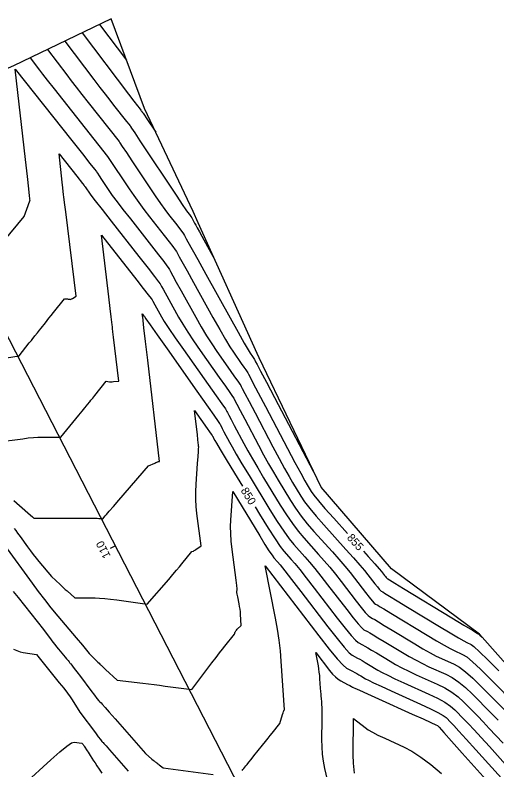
# Model space of a CAD drawing. Extents: x 1715724 to 1716561, y 394063 to 395906.
# Drawn here: x 1715894.2 to 1715978.1, y 395302.7 to 395434.3 of the extents above; entities that cross this region are included whole.
import ezdxf

# ---------------------------------------------------------------- set-up
doc = ezdxf.new("R2010")
doc.units = 0
for name, color, linetype in [('DT_X_Contour_Major', 7, 'Continuous'), ('DT_X_Contour_Minor', 7, 'Continuous'), ('DT_X_TIN_Hull', 7, 'Continuous'), ('GE_P_CL_10', 7, 'Continuous')]:
    doc.layers.add(name, color=color, linetype=linetype)

msp = doc.modelspace()

# ---------------------------------------------------------------- linework, layer by layer
at = {"layer": 'DT_X_Contour_Major'}
for points in [[(1715896.77, 395426.83), (1715898.41, 395424.66), (1715898.92, 395423.99), (1715899.77, 395422.9), (1715900.95, 395421.41), (1715902.46, 395419.51), (1715910.28, 395409.64), (1715914.02, 395404), (1715914.85, 395402.79), (1715915.71, 395401.57), (1715916.61, 395400.35), (1715917.56, 395399.12), (1715920.13, 395395.85), (1715920.99, 395394.75), (1715921.63, 395393.92), (1715922.05, 395393.35), (1715922.26, 395393.05), (1715922.51, 395392.59), (1715922.75, 395392.15), (1715924.12, 395389.68), (1715925.24, 395387.66), (1715928.63, 395381.54), (1715929.81, 395379.44), (1715930.8, 395377.73), (1715931.6, 395376.42), (1715932.21, 395375.49), (1715933.58, 395373.54), (1715934.04, 395372.89), (1715934.38, 395372.4), (1715934.6, 395372.08), (1715934.7, 395371.91), (1715934.82, 395371.68), (1715935.04, 395371.26), (1715935.61, 395370.18), (1715936.53, 395368.44), (1715937.79, 395366.03), (1715941.64, 395358.72), (1715942.93, 395356.27), (1715943.93, 395354.4), (1715944.64, 395353.1), (1715945.05, 395352.37), (1715945.76, 395351.21), (1715946.2, 395350.59), (1715947, 395349.61), (1715948.16, 395348.27), (1715949.68, 395346.57), (1715952.07, 395343.93)], [(1715894, 395344.79), (1715894.28, 395344.41), (1715894.59, 395343.98), (1715895.03, 395343.37), (1715896.34, 395341.55), (1715896.84, 395340.88), (1715897.32, 395340.24), (1715897.81, 395339.63), (1715898.29, 395339.05), (1715900.52, 395336.4), (1715902, 395335.01), (1715902.31, 395334.71), (1715902.61, 395334.43), (1715902.91, 395334.15), (1715903.21, 395333.89), (1715904.56, 395332.67), (1715908.09, 395332.66), (1715908.89, 395332.64), (1715909.79, 395332.58), (1715910.79, 395332.47), (1715911.88, 395332.33), (1715917.2, 395331.57), (1715920.92, 395335.88), (1715921.67, 395336.74), (1715922.3, 395337.49), (1715922.82, 395338.12), (1715923.24, 395338.63), (1715924.93, 395340.74), (1715925.16, 395340.82), (1715925.23, 395340.85), (1715925.34, 395340.91), (1715925.48, 395341), (1715925.67, 395341.12), (1715926.6, 395341.74), (1715925.84, 395347.36), (1715925.71, 395348.59), (1715925.65, 395349.85), (1715925.65, 395351.15), (1715925.71, 395352.49), (1715925.96, 395356.12), (1715926.04, 395357.32), (1715926.1, 395358.19), (1715926.14, 395358.74), (1715926.15, 395358.97), (1715926.14, 395359.15), (1715926.13, 395359.33), (1715926.08, 395359.71), (1715926.02, 395360.3), (1715925.92, 395361.1), (1715925.43, 395365.34), (1715927.62, 395362.22), (1715928.03, 395361.64), (1715928.33, 395361.22), (1715928.51, 395360.97), (1715928.57, 395360.88), (1715928.58, 395360.87), (1715928.59, 395360.84), (1715928.62, 395360.78), (1715928.67, 395360.68), (1715928.74, 395360.54), (1715928.96, 395360.13), (1715929.24, 395359.66), (1715929.91, 395358.55), (1715930.96, 395356.81), (1715932.4, 395354.44), (1715933.79, 395352.15)], [(1715935.97, 395348.56), (1715936.76, 395347.26), (1715938.26, 395344.84), (1715939.46, 395342.96), (1715940.37, 395341.61), (1715941, 395340.81), (1715942.28, 395339.39), (1715942.89, 395338.68), (1715943.76, 395337.61), (1715944.89, 395336.18), (1715946.27, 395334.39), (1715950.31, 395329.15), (1715951.68, 395327.41), (1715952.73, 395326.12), (1715953.48, 395325.29), (1715953.93, 395324.9), (1715954.72, 395324.49), (1715955.09, 395324.29), (1715955.61, 395323.99), (1715956.28, 395323.59), (1715957.11, 395323.09), (1715959.51, 395321.63), (1715960.47, 395321.07), (1715961.55, 395320.49), (1715962.75, 395319.9), (1715964.07, 395319.29), (1715967.73, 395317.64), (1715969.05, 395316.98), (1715970.26, 395316.24), (1715971.34, 395315.43), (1715972.32, 395314.54), (1715974.77, 395312.05), (1715975.74, 395311.06), (1715976.79, 395309.94), (1715977.94, 395308.7), (1715979.19, 395307.33)], [(1715954.88, 395340.81), (1715955.71, 395339.89), (1715956.85, 395338.62), (1715957.61, 395337.75), (1715957.99, 395337.29), (1715958.51, 395336.61), (1715958.69, 395336.39), (1715958.83, 395336.22), (1715958.93, 395336.11), (1715958.98, 395336.06), (1715959.09, 395336.01), (1715959.42, 395335.81), (1715960.33, 395335.25), (1715961.84, 395334.34), (1715970.28, 395329.2), (1715972.37, 395327.94), (1715973.86, 395327.03), (1715974.76, 395326.48), (1715975.06, 395326.3), (1715975.07, 395326.3), (1715975.09, 395326.29), (1715975.11, 395326.26), (1715975.53, 395325.84)]]:
    msp.add_lwpolyline(points, dxfattribs=at)
at = {"layer": 'DT_X_Contour_Minor'}
for points in [[(1715908.89, 395432.64), (1715913.57, 395426.43)], [(1715905.86, 395431.19), (1715913.92, 395420.5), (1715914.87, 395419.25), (1715915.48, 395418.44), (1715915.76, 395418.08), (1715916.05, 395417.7), (1715916.15, 395417.58), (1715916.22, 395417.5), (1715916.26, 395417.44), (1715916.27, 395417.43), (1715916.27, 395417.43), (1715916.32, 395417.36), (1715916.45, 395417.16), (1715916.68, 395416.82), (1715916.99, 395416.35), (1715918.66, 395413.83)], [(1715902.83, 395429.74), (1715907.89, 395423.02), (1715908.92, 395421.66), (1715909.83, 395420.47), (1715910.64, 395419.43), (1715911.32, 395418.55), (1715913.56, 395415.73), (1715913.95, 395415.23), (1715914.19, 395414.93), (1715914.27, 395414.83), (1715914.27, 395414.83), (1715914.46, 395414.55), (1715915, 395413.73), (1715915.91, 395412.37), (1715917.18, 395410.45), (1715921.05, 395404.62), (1715922.33, 395402.69), (1715923.29, 395401.26), (1715923.91, 395400.34), (1715924.2, 395399.93), (1715924.53, 395399.51), (1715924.66, 395399.33), (1715924.79, 395399.14), (1715924.93, 395398.92), (1715925.07, 395398.67), (1715925.45, 395397.98), (1715925.64, 395397.65), (1715925.91, 395397.16), (1715926.27, 395396.51), (1715926.71, 395395.71), (1715928.99, 395391.6)], [(1715899.8, 395428.29), (1715903.15, 395423.84), (1715903.92, 395422.82), (1715904.8, 395421.68), (1715905.79, 395420.42), (1715906.89, 395419.03), (1715912.27, 395412.24), (1715912.28, 395412.23), (1715912.42, 395412.02), (1715912.84, 395411.38), (1715913.55, 395410.32), (1715914.53, 395408.83), (1715917.54, 395404.31), (1715918.59, 395402.74), (1715919.5, 395401.42), (1715920.26, 395400.35), (1715920.88, 395399.53), (1715922.33, 395397.68), (1715922.82, 395397.04), (1715923.21, 395396.53), (1715923.49, 395396.14), (1715923.66, 395395.86), (1715923.98, 395395.29), (1715924.28, 395394.74), (1715925.99, 395391.66), (1715927.39, 395389.13), (1715931.62, 395381.5), (1715933.03, 395378.97), (1715934.08, 395377.1), (1715934.77, 395375.89), (1715935.1, 395375.34), (1715935.51, 395374.76), (1715935.65, 395374.55), (1715935.77, 395374.38), (1715935.86, 395374.23), (1715935.93, 395374.11), (1715936.07, 395373.84), (1715936.32, 395373.38), (1715936.94, 395372.18), (1715937.95, 395370.26), (1715939.35, 395367.61), (1715946.74, 395353.56)], [(1715892.11, 395394.81), (1715895.72, 395399.13), (1715896.42, 395401.07), (1715896.55, 395401.44), (1715896.65, 395401.7), (1715896.71, 395401.86), (1715896.74, 395401.92), (1715896.77, 395401.94), (1715896.74, 395402.2), (1715896.74, 395402.25), (1715896.73, 395402.29), (1715896.73, 395402.31), (1715896.73, 395402.31), (1715896.73, 395402.31), (1715896.68, 395402.74), (1715896.54, 395404), (1715896.3, 395406.12), (1715895.96, 395409.07), (1715894.17, 395424.84), (1715904.03, 395412.4), (1715905.88, 395410.07), (1715907.21, 395408.4), (1715908, 395407.4), (1715908.27, 395407.06), (1715908.28, 395407.04), (1715908.34, 395406.95), (1715908.53, 395406.68), (1715908.82, 395406.23), (1715909.24, 395405.6), (1715910.51, 395403.68), (1715911.1, 395402.84), (1715911.92, 395401.73), (1715912.96, 395400.36), (1715914.24, 395398.72), (1715917.93, 395394.02), (1715919.15, 395392.46), (1715920.05, 395391.31), (1715920.61, 395390.57), (1715920.85, 395390.24), (1715921.04, 395389.89), (1715921.22, 395389.56), (1715921.63, 395388.83), (1715922.25, 395387.71), (1715923.1, 395386.18), (1715925.65, 395381.58), (1715926.59, 395379.92), (1715927.52, 395378.37), (1715928.43, 395376.95), (1715929.31, 395375.64), (1715931.65, 395372.33), (1715932.42, 395371.23), (1715932.98, 395370.43), (1715933.33, 395369.92), (1715933.48, 395369.7), (1715933.57, 395369.52), (1715933.75, 395369.18), (1715934.21, 395368.3), (1715934.96, 395366.89), (1715935.98, 395364.93), (1715939.1, 395359.01), (1715940.19, 395356.95), (1715941.13, 395355.23), (1715941.9, 395353.84), (1715942.52, 395352.78), (1715943.96, 395350.42), (1715944.61, 395349.44), (1715945.49, 395348.28), (1715946.61, 395346.94), (1715947.94, 395345.42), (1715951.82, 395341.13), (1715953.15, 395339.64), (1715954.23, 395338.41), (1715955.06, 395337.44), (1715955.65, 395336.71), (1715956.87, 395335.12), (1715957.29, 395334.59), (1715957.61, 395334.2), (1715957.84, 395333.95), (1715957.97, 395333.83), (1715958.21, 395333.71), (1715958.55, 395333.51), (1715959.39, 395333), (1715960.73, 395332.19), (1715962.56, 395331.07), (1715968.13, 395327.69), (1715969.99, 395326.56), (1715971.4, 395325.72), (1715972.36, 395325.17), (1715972.86, 395324.9), (1715973.61, 395324.56), (1715974.12, 395324.18), (1715975.09, 395323.29), (1715976.53, 395321.9), (1715978.43, 395319.99)], [(1715887.81, 395373.78), (1715894.86, 395374.88), (1715896.64, 395377.12), (1715896.99, 395377.55), (1715897.27, 395377.9), (1715897.48, 395378.17), (1715897.62, 395378.35), (1715898.04, 395378.88), (1715898.22, 395379.1), (1715898.43, 395379.37), (1715898.69, 395379.7), (1715899.43, 395380.64), (1715899.73, 395381.02), (1715900.06, 395381.43), (1715900.43, 395381.89), (1715900.83, 395382.4), (1715902.78, 395384.83), (1715903.28, 395384.78), (1715903.38, 395384.77), (1715903.45, 395384.76), (1715903.5, 395384.75), (1715903.54, 395384.75), (1715903.59, 395384.74), (1715903.61, 395384.73), (1715903.64, 395384.73), (1715903.66, 395384.72), (1715903.7, 395384.72), (1715903.79, 395384.7), (1715903.84, 395384.71), (1715903.91, 395384.74), (1715904.01, 395384.8), (1715904.14, 395384.87), (1715904.8, 395385.29), (1715902.99, 395399.96), (1715902.79, 395401.62), (1715902.67, 395402.61), (1715902.62, 395402.95), (1715902.62, 395402.97), (1715902.56, 395403.51), (1715902.48, 395404.18), (1715902.38, 395405.11), (1715901.81, 395410.08), (1715904.93, 395406.16), (1715905.93, 395404.9), (1715906.18, 395404.58), (1715906.27, 395404.46), (1715906.28, 395404.45), (1715906.31, 395404.41), (1715906.37, 395404.32), (1715906.46, 395404.18), (1715906.6, 395403.98), (1715907, 395403.37), (1715907.36, 395402.89), (1715908.13, 395401.88), (1715909.31, 395400.36), (1715910.91, 395398.32), (1715915.73, 395392.19), (1715917.32, 395390.17), (1715918.47, 395388.71), (1715919.17, 395387.79), (1715919.44, 395387.43), (1715919.57, 395387.19), (1715919.69, 395386.97), (1715919.96, 395386.48), (1715920.95, 395384.71), (1715922.66, 395381.62), (1715923.37, 395380.39), (1715924.24, 395379.01), (1715925.25, 395377.48), (1715926.42, 395375.8), (1715929.72, 395371.12), (1715930.8, 395369.57), (1715931.59, 395368.46), (1715932.07, 395367.76), (1715932.25, 395367.5), (1715932.46, 395367.09), (1715932.81, 395366.42), (1715933.39, 395365.33), (1715934.17, 395363.84), (1715936.57, 395359.29), (1715937.45, 395357.63), (1715938.32, 395356.06), (1715939.17, 395354.58), (1715939.99, 395353.2), (1715942.16, 395349.63), (1715943.02, 395348.29), (1715943.99, 395346.95), (1715945.05, 395345.61), (1715946.21, 395344.27), (1715949.44, 395340.69), (1715950.59, 395339.4), (1715951.61, 395338.21), (1715952.52, 395337.12), (1715953.3, 395336.13), (1715955.23, 395333.63), (1715955.88, 395332.79), (1715956.39, 395332.18), (1715956.75, 395331.78), (1715956.96, 395331.6), (1715957.34, 395331.4), (1715957.68, 395331.2), (1715958.44, 395330.75), (1715959.62, 395330.04), (1715965.98, 395326.17), (1715967.61, 395325.19), (1715968.94, 395324.41), (1715969.96, 395323.85), (1715970.66, 395323.5), (1715972.14, 395322.83), (1715972.85, 395322.38), (1715973.88, 395321.53), (1715975.23, 395320.28), (1715976.91, 395318.62), (1715981.79, 395313.68)], [(1715890.77, 395359.81), (1715895.48, 395360.43), (1715896.45, 395360.55), (1715897.34, 395360.63), (1715898.15, 395360.68), (1715898.88, 395360.7), (1715902.12, 395360.69), (1715905.26, 395364.51), (1715905.86, 395365.24), (1715906.31, 395365.79), (1715906.62, 395366.17), (1715906.79, 395366.37), (1715907.17, 395366.85), (1715907.38, 395367.12), (1715907.68, 395367.49), (1715908.06, 395367.97), (1715910.03, 395370.43), (1715910.63, 395370.36), (1715910.77, 395370.35), (1715910.92, 395370.35), (1715911.09, 395370.35), (1715911.28, 395370.37), (1715912.21, 395370.44), (1715911.32, 395378.11), (1715911.21, 395379.03), (1715911.14, 395379.63), (1715911.11, 395379.92), (1715911.06, 395380.28), (1715910.9, 395381.64), (1715910.72, 395383.13), (1715910.48, 395385.16), (1715909.19, 395395.89), (1715915.35, 395388.06), (1715916.5, 395386.59), (1715917.34, 395385.52), (1715917.85, 395384.86), (1715918.03, 395384.61), (1715918.1, 395384.5), (1715918.16, 395384.38), (1715918.51, 395383.75), (1715918.8, 395383.23), (1715919.67, 395381.66), (1715920.16, 395380.86), (1715920.96, 395379.65), (1715922.08, 395378.01), (1715923.52, 395375.95), (1715927.79, 395369.9), (1715929.19, 395367.91), (1715930.19, 395366.48), (1715930.8, 395365.61), (1715931.02, 395365.29), (1715931.07, 395365.19), (1715931.17, 395365.01), (1715931.42, 395364.54), (1715931.81, 395363.78), (1715932.36, 395362.74), (1715934.03, 395359.57), (1715934.72, 395358.3), (1715935.52, 395356.89), (1715936.43, 395355.32), (1715937.46, 395353.61), (1715940.36, 395348.84), (1715941.43, 395347.14), (1715942.48, 395345.62), (1715943.49, 395344.28), (1715944.47, 395343.12), (1715947.05, 395340.26), (1715948.02, 395339.16), (1715949, 395338.01), (1715949.98, 395336.81), (1715950.96, 395335.55), (1715953.59, 395332.13), (1715954.48, 395331), (1715955.17, 395330.16), (1715955.66, 395329.62), (1715955.95, 395329.37), (1715956.46, 395329.1), (1715956.82, 395328.9), (1715957.5, 395328.49), (1715958.5, 395327.89), (1715959.84, 395327.08), (1715963.82, 395324.66), (1715965.23, 395323.82), (1715966.48, 395323.11), (1715967.55, 395322.53), (1715968.46, 395322.09), (1715970.67, 395321.1), (1715971.58, 395320.58), (1715972.67, 395319.77), (1715973.94, 395318.66), (1715975.38, 395317.26), (1715979.45, 395313.14)], [(1715893.94, 395349.63), (1715896.38, 395347.49), (1715896.84, 395347.09), (1715897.17, 395346.8), (1715897.36, 395346.63), (1715897.43, 395346.57), (1715897.45, 395346.56), (1715897.52, 395346.57), (1715897.57, 395346.57), (1715897.68, 395346.57), (1715897.87, 395346.57), (1715898.87, 395346.57), (1715899.24, 395346.57), (1715899.79, 395346.56), (1715900.52, 395346.56), (1715901.42, 395346.56), (1715904.99, 395346.55), (1715905.77, 395346.55), (1715906.41, 395346.55), (1715906.91, 395346.55), (1715908.05, 395346.55), (1715908.44, 395346.55), (1715908.74, 395346.54), (1715908.95, 395346.53), (1715909.07, 395346.52), (1715909.43, 395346.47), (1715909.86, 395346.97), (1715910.08, 395347.23), (1715910.55, 395347.77), (1715911.28, 395348.61), (1715912.26, 395349.73), (1715917.43, 395355.67), (1715918.49, 395356.16), (1715918.69, 395356.25), (1715918.85, 395356.32), (1715918.96, 395356.37), (1715919.03, 395356.4), (1715919.16, 395356.44), (1715919.2, 395356.45), (1715919.24, 395356.47), (1715919.25, 395356.47), (1715919.26, 395356.47), (1715919.26, 395356.47), (1715919.26, 395356.47), (1715919.27, 395356.47), (1715919.31, 395356.47), (1715917.27, 395374.09), (1715916.88, 395377.39), (1715916.61, 395379.75), (1715916.39, 395381.64), (1715916.39, 395381.66), (1715916.39, 395381.67), (1715916.38, 395381.7), (1715916.38, 395381.75), (1715916.37, 395381.82), (1715916.33, 395382.19), (1715916.54, 395381.92), (1715916.58, 395381.87), (1715916.6, 395381.83), (1715916.62, 395381.81), (1715916.63, 395381.8), (1715916.63, 395381.8), (1715916.63, 395381.8), (1715916.64, 395381.79), (1715916.64, 395381.77), (1715916.65, 395381.76), (1715916.68, 395381.7), (1715916.94, 395381.34), (1715917.68, 395380.28), (1715918.91, 395378.54), (1715920.63, 395376.1), (1715925.85, 395368.69), (1715928.8, 395364.51), (1715929.54, 395363.45), (1715929.8, 395363.09), (1715929.82, 395363.03), (1715929.88, 395362.93), (1715930.24, 395362.23), (1715930.55, 395361.64), (1715931.5, 395359.85), (1715931.98, 395358.98), (1715932.71, 395357.72), (1715933.69, 395356.07), (1715934.93, 395354.02), (1715938.56, 395348.05), (1715939.84, 395345.99), (1715940.97, 395344.29), (1715941.93, 395342.95), (1715942.74, 395341.96), (1715944.67, 395339.82), (1715945.46, 395338.92), (1715946.38, 395337.81), (1715947.43, 395336.49), (1715948.62, 395334.97), (1715951.95, 395330.64), (1715953.08, 395329.2), (1715953.95, 395328.14), (1715954.57, 395327.45), (1715954.94, 395327.14), (1715955.59, 395326.8), (1715955.95, 395326.59), (1715956.55, 395326.24), (1715957.39, 395325.74), (1715958.47, 395325.08), (1715961.67, 395323.14), (1715962.85, 395322.44), (1715964.02, 395321.8), (1715965.15, 395321.22), (1715966.27, 395320.69), (1715969.2, 395319.37), (1715970.32, 395318.78), (1715971.46, 395318), (1715972.64, 395317.04), (1715973.85, 395315.9), (1715977.11, 395312.6), (1715978.31, 395311.37)], [(1715892.34, 395341.85), (1715897.13, 395335.22), (1715898.18, 395333.79), (1715899.27, 395332.37), (1715900.41, 395330.94), (1715901.6, 395329.51), (1715904.82, 395325.69), (1715905.88, 395324.43), (1715906.63, 395323.54), (1715907.08, 395323), (1715907.24, 395322.82), (1715907.24, 395322.81), (1715907.24, 395322.81), (1715907.25, 395322.8), (1715907.27, 395322.78), (1715907.29, 395322.76), (1715907.39, 395322.63), (1715908.56, 395321.5), (1715908.78, 395321.29), (1715908.93, 395321.14), (1715909.06, 395321.02), (1715909.06, 395321.01), (1715909.06, 395321.01), (1715909.06, 395321.01), (1715909.06, 395321.01), (1715909.07, 395321.01), (1715909.07, 395321.01), (1715909.07, 395321.01), (1715909.13, 395320.96), (1715909.29, 395320.81), (1715909.56, 395320.56), (1715909.94, 395320.21), (1715911.97, 395318.35), (1715916.44, 395317.8), (1715917.4, 395317.68), (1715918.37, 395317.56), (1715919.35, 395317.44), (1715920.33, 395317.32), (1715924.93, 395316.73), (1715928.47, 395321.36), (1715929.18, 395322.29), (1715929.79, 395323.08), (1715930.3, 395323.73), (1715930.71, 395324.25), (1715932.41, 395326.36), (1715932.53, 395326.75), (1715932.57, 395326.84), (1715932.64, 395326.95), (1715932.74, 395327.06), (1715932.88, 395327.2), (1715933.58, 395327.84), (1715933.45, 395329.83), (1715933.41, 395330.26), (1715933.36, 395330.71), (1715933.29, 395331.16), (1715933.2, 395331.63), (1715932.95, 395332.89), (1715932.87, 395333.31), (1715932.82, 395333.62), (1715932.81, 395333.82), (1715932.82, 395333.91), (1715932.88, 395334.02), (1715932.88, 395334.24), (1715932.82, 395334.83), (1715932.71, 395335.78), (1715932.53, 395337.1), (1715932, 395341.1), (1715931.83, 395342.54), (1715931.73, 395343.88), (1715931.7, 395345.11), (1715931.74, 395346.23), (1715932.09, 395351.2), (1715936.78, 395343.49), (1715937.69, 395342.01), (1715938.4, 395340.88), (1715938.93, 395340.1), (1715939.26, 395339.66), (1715939.9, 395338.95), (1715940.33, 395338.43), (1715941.15, 395337.4), (1715942.35, 395335.86), (1715943.93, 395333.81), (1715948.67, 395327.65), (1715950.27, 395325.61), (1715951.51, 395324.1), (1715952.4, 395323.12), (1715952.92, 395322.67), (1715953.84, 395322.19), (1715954.22, 395321.99), (1715954.66, 395321.74), (1715955.17, 395321.44), (1715955.74, 395321.09), (1715957.36, 395320.11), (1715958.1, 395319.7), (1715959.09, 395319.19), (1715960.35, 395318.58), (1715961.87, 395317.89), (1715966.27, 395315.9), (1715967.78, 395315.18), (1715969.05, 395314.48), (1715970.05, 395313.81), (1715970.79, 395313.17), (1715972.43, 395311.51), (1715973.17, 395310.75), (1715974.14, 395309.7), (1715975.36, 395308.37), (1715976.82, 395306.76), (1715981.03, 395302.09)], [(1715933.74, 395302.61), (1715933.87, 395302.77), (1715934.01, 395302.95), (1715934.38, 395303.41), (1715934.57, 395303.65), (1715934.87, 395304.02), (1715935.27, 395304.52), (1715935.77, 395305.15), (1715937.26, 395307.01), (1715937.79, 395307.66), (1715938.24, 395308.23), (1715938.63, 395308.72), (1715938.95, 395309.11), (1715940.28, 395310.77), (1715940.76, 395312.35), (1715940.85, 395312.65), (1715940.92, 395312.87), (1715940.98, 395313.01), (1715941.01, 395313.07), (1715941.12, 395313.17), (1715940.54, 395321.63), (1715940.39, 395323.46), (1715940.16, 395325.32), (1715939.88, 395327.22), (1715939.52, 395329.15), (1715937.72, 395338.25), (1715947.1, 395326.07), (1715948.91, 395323.77), (1715950.31, 395322.06), (1715951.31, 395320.95), (1715951.91, 395320.44), (1715952.97, 395319.89), (1715953.35, 395319.68), (1715953.72, 395319.48), (1715954.06, 395319.29), (1715954.38, 395319.1), (1715955.21, 395318.59), (1715955.72, 395318.32), (1715956.63, 395317.88), (1715957.95, 395317.27), (1715959.67, 395316.48), (1715964.8, 395314.17), (1715966.52, 395313.37), (1715967.84, 395312.71), (1715968.75, 395312.19), (1715969.26, 395311.81), (1715970.09, 395310.97), (1715970.6, 395310.44), (1715971.49, 395309.46), (1715972.78, 395308.05), (1715974.45, 395306.19), (1715979.43, 395300.66)], [(1715893.8, 395333.8), (1715894.67, 395332.72), (1715899.13, 395327.19), (1715900.47, 395325.35), (1715900.76, 395324.96), (1715901.06, 395324.56), (1715901.38, 395324.16), (1715901.71, 395323.76), (1715902.6, 395322.7), (1715902.9, 395322.34), (1715903.14, 395322.06), (1715903.3, 395321.86), (1715903.4, 395321.74), (1715903.58, 395321.51), (1715903.65, 395321.43), (1715903.71, 395321.35), (1715903.78, 395321.26), (1715903.85, 395321.18), (1715904.04, 395320.96), (1715904.18, 395320.78), (1715904.48, 395320.38), (1715904.93, 395319.78), (1715905.54, 395318.98), (1715907.36, 395316.55), (1715907.97, 395315.74), (1715908.43, 395315.14), (1715908.74, 395314.75), (1715908.9, 395314.57), (1715909.13, 395314.36), (1715909.35, 395314.13), (1715909.83, 395313.59), (1715910.58, 395312.75), (1715911.58, 395311.6), (1715916.89, 395305.53), (1715918.01, 395304.59), (1715918.23, 395304.41), (1715918.39, 395304.27), (1715918.51, 395304.18), (1715918.58, 395304.12), (1715918.69, 395304.04), (1715918.73, 395304), (1715918.76, 395303.97), (1715918.8, 395303.95), (1715918.83, 395303.92), (1715918.9, 395303.86), (1715918.94, 395303.83), (1715919.02, 395303.77), (1715919.12, 395303.69), (1715919.26, 395303.58), (1715919.98, 395303.03), (1715928.67, 395301.91)], [(1715893.86, 395323.74), (1715894.49, 395323.48), (1715895.06, 395323.29), (1715895.58, 395323.17), (1715897.9, 395322.81), (1715901.86, 395317.9), (1715902.64, 395316.92), (1715903.28, 395316.1), (1715903.77, 395315.42), (1715904.13, 395314.89), (1715905.44, 395312.77), (1715908.15, 395309.16), (1715908.66, 395308.48), (1715909.04, 395307.98), (1715909.28, 395307.67), (1715909.38, 395307.55), (1715909.48, 395307.46), (1715909.63, 395307.3), (1715910, 395306.88), (1715910.59, 395306.21), (1715911.4, 395305.28), (1715913.85, 395302.47)], [(1715949.46, 395297.22), (1715948.15, 395302.97), (1715947.91, 395304.21), (1715947.73, 395305.46), (1715947.64, 395306.73), (1715947.61, 395308), (1715947.64, 395311.43), (1715947.65, 395312.59), (1715947.64, 395313.49), (1715947.63, 395314.13), (1715947.61, 395314.51), (1715947.54, 395315.18), (1715947.51, 395315.48), (1715947.48, 395315.87), (1715947.44, 395316.35), (1715947.4, 395316.92), (1715947.29, 395318.58), (1715947.24, 395319.18), (1715947.17, 395319.76), (1715947.09, 395320.31), (1715947, 395320.83), (1715946.54, 395323.18), (1715948.96, 395320.03), (1715949.47, 395319.41), (1715949.97, 395318.9), (1715950.44, 395318.5), (1715950.9, 395318.21), (1715952.09, 395317.58), (1715952.49, 395317.38), (1715952.77, 395317.23), (1715952.95, 395317.14), (1715953.02, 395317.1), (1715953.05, 395317.08), (1715953.34, 395316.95), (1715954.17, 395316.57), (1715955.55, 395315.95), (1715957.47, 395315.08), (1715963.33, 395312.44), (1715965.25, 395311.57), (1715966.63, 395310.95), (1715967.46, 395310.58), (1715967.74, 395310.45), (1715967.75, 395310.43), (1715968.03, 395310.12), (1715968.84, 395309.22), (1715970.19, 395307.72), (1715972.08, 395305.62), (1715977.84, 395299.23)], [(1715953.32, 395302.15), (1715953.13, 395303.86), (1715953.07, 395305.33), (1715953.13, 395311.63), (1715955.15, 395310.07), (1715955.69, 395309.7), (1715956.43, 395309.27), (1715957.39, 395308.78), (1715958.56, 395308.23), (1715961.95, 395306.68), (1715963.32, 395305.95), (1715964.86, 395304.94), (1715966.58, 395303.64), (1715968.49, 395302.05)], [(1715895.66, 395300.16), (1715900.38, 395304.44), (1715901.96, 395305.84), (1715903.17, 395306.83), (1715904.01, 395307.4), (1715904.48, 395307.56), (1715905.81, 395307.35), (1715906.02, 395307.1), (1715906.07, 395307.03), (1715906.13, 395306.94), (1715906.22, 395306.81), (1715906.32, 395306.65), (1715906.6, 395306.19), (1715906.72, 395306), (1715906.87, 395305.77), (1715907.05, 395305.5), (1715907.25, 395305.18), (1715907.84, 395304.3), (1715908.09, 395303.91), (1715908.41, 395303.43), (1715908.8, 395302.84), (1715909.26, 395302.15)]]:
    msp.add_lwpolyline(points, dxfattribs=at)
at = {"layer": 'DT_X_TIN_Hull'}
msp.add_lwpolyline([(1716036.81, 395207.99), (1716026.44, 395229.43), (1716015.95, 395249.24), (1716007.82, 395269.9), (1716003.67, 395274.88), (1716001.74, 395288.94), (1715989.7, 395309.86), (1715975.1, 395326.33), (1715959.74, 395337.73), (1715947.5, 395351.97), (1715936.7, 395374.51), (1715936.34, 395375.27), (1715926.08, 395398.06), (1715925.19, 395400.05), (1715916.7, 395417.97), (1715910.92, 395433.61), (1715893.86, 395425.44), (1715886.84, 395422.34), (1715877.89, 395436.06)], dxfattribs=at)
at = {"layer": 'GE_P_CL_10'}
for p, q in [((1716249.46, 394685.42), (1715852.54, 395456.56)), ((1715911.63, 395341.77), (1715910.74, 395341.31))]:
    msp.add_line(p, q, dxfattribs=at)

# ---------------------------------------------------------------- texts
at = {"layer": 'DT_X_Contour_Major'}
for s, rotation, p in [('850', 301.3032, (1715933.42, 395351.41)), ('855', 312.0453, (1715951.89, 395343.09))]:
    msp.add_text(s, height=1.4, rotation=rotation, dxfattribs=at).set_placement(p)
at = {"layer": 'GE_P_CL_10'}
msp.add_text('110', height=1.4, rotation=117.2357, dxfattribs=at).set_placement((1715910.85, 395340))

doc.saveas('drawing.dxf')
